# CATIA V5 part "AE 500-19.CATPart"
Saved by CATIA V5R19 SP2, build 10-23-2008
Part number: AE 500-19
Bounding box of the stored display mesh (mm): x -22.494 to 22.494, y -22.494 to 22.494, z 0 to 88
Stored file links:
  C:\Users\Bora\Desktop\3D Katı model\AE serisi\AE 500\AE 500-19.CATPart
  C:\Program Files\Dassault Systemes\B19\intel_a\reffiles\standard\MetricThickPitch.txt
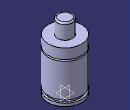
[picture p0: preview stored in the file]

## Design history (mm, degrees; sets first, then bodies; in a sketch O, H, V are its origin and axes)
Body1 (main body)
  Sketch1 on yz-plane, origin (0, 0, 0), H (0, 1, 0), V (0, 0, 1)
    point P1 (22.5, 52.5)
    point P8 (22.5, 54.5)
    point P9 (22.5, 54.5)
    point P10 (22.5, 52.5)
    point P11 (10, 86)
    point P13 (10, 86)
    line L1 (22.5, 52.5) -> (22.5, 8)
    line L2 (22.5, 4) -> (22.5, 0)
    line L3 (20, 8) -> (20, 4)
    line L4 (22.5, 68) -> (22.5, 54.5)
    arc A1 centre (22.5, 53.5) radius 1 from (22.5, 54.5) to (22.5, 52.5) ccw
    line L5 (10, 86) -> (10, 68)
    arc A2 centre (8, 86) radius 2 from (10, 86) to (8, 88) ccw
    line L6 (8, 88) -> (0, 88)
    point P15 (0, 88)
    line L7 (10, 68) -> (22.5, 68)
    line L8 (0, 0) -> (22.5, 0)
    line L9 (20, 8) -> (22.5, 8)
    line L10 (20, 4) -> (22.5, 4)
    coincidence: P15 V, P1 P10, P8 P9, P11 P13
    tangency: L6 A2
    horizontal: L7 H, L8 H, L9 H, L10 H
  Shaft1: profile Sketch1, axis Sketch1.V, angle 360
  Sketch2 on face of Shaft1 from Sketch1.L8, origin (0, 0, 0), H (1, 0, 0), V (0, -1, 0)
    point P1 (10, 0)
    distance P1 V = 10
  Hole1: placed by Sketch2, at (10, 0, 0) direction (0, 0, 1), diameter 6.647, depth 13, threaded "M8", thread diameter 8, thread depth 13, pitch 1.25
  CircPattern1: of Hole1, instances 2, angular step 180, axis from xy-plane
